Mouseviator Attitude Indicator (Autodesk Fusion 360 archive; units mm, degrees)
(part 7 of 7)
sketch "Wings!" plane through (0, 0, 0) normal (0, 1, 0) x axis (1, 0, 0)
  line L1 (520.32, -294.692) -> (520.32, -232.0032)
  line L2 (525.7316, -110.9551) -> (520.7141, -110.955)
  line L3 (520.7148, -79.9338) -> (500, -79.9338)
  line L4 (525.7287, -224.0816) -> (525.7316, -107.4016)
  line L5 (511.0057, -228.9584) -> (511.005, -224.0813)
  line L6 (511.005, -224.0813) -> (525.7287, -224.0816)
  line L7 (520.3202, -224.0815) -> (520.32, -232.0032)
  line L8 (520.7141, -110.955) -> (520.7148, -79.9338)
  line L9 (520.32, -228.9584) -> (511.0057, -228.9584)
  line L10 (500, -294.692) -> (500, -79.9338)
  line L11 (-520.32, -224.0816) -> (-520.32, -228.9584)
  line L12 (-526.6736, -224.1265) -> (-526.6736, -105.4918)
  line L13 (-513.7068, -224.0816) -> (-526.6736, -224.0816)
  line L14 (-522.3504, -105.4918) -> (-522.3504, -79.9338)
  line L15 (-526.6736, -105.4918) -> (-522.3504, -105.4918)
  line L16 (-522.3504, -79.9338) -> (-500, -79.9338)
  line L17 (-513.7068, -228.9584) -> (-513.7068, -224.0816)
  line L18 (-500, -294.692) -> (-500, -79.9338)
  line L19 (-520.32, -253.4337) -> (-520.32, -228.9584)
  line L20 (-520.32, -294.692) -> (-520.32, -253.4337)
  line L21 (-520.32, -228.9584) -> (-513.7068, -228.9584)
  curve K1 (172.9706, -420) -> (500, -294.703)
  line L22 (172.9706, -420) -> (0, -420)
  line L23 (-172.9706, -420) -> (0, -420)
  curve K2 (-172.9706, -420) -> (-500, -294.703)
  curve K3 (172.9706, -440.32) -> (520.32, -294.703)
  line L24 (172.9706, -440.32) -> (0, -440.32)
  line L25 (-172.9706, -440.32) -> (0, -440.32)
  curve K4 (-172.9706, -440.32) -> (-520.32, -294.703)
  line L26 (-499.9986, -293.6669) -> (-499.9986, -295.0337)
  line L27 (-520.3191, -293.2676) -> (-520.3191, -295.0337)
  line L28 (500, -294.692) -> (500, -294.703)
  line L29 (520.32, -294.692) -> (520.32, -294.703)
  line L30 (-500, -294.692) -> (-500, -294.703)
  line L31 (-520.32, -294.703) -> (-520.32, -294.692)
  circle C1 centre (511.1752, -213.2838) radius 3.81
  circle C2 centre (511.1752, -162.4838) radius 3.81
  circle C3 centre (511.1752, -105.3338) radius 3.81
  arc A1 centre (509.464, -135.4622) radius 12.7 clockwise from (500, -126.9933) to (500, -143.9311)
  circle C4 centre (-511.1752, -213.2838) radius 3.81
  circle C5 centre (-511.1752, -162.4838) radius 3.81
  circle C6 centre (-511.1752, -105.3338) radius 3.81
  arc A2 centre (-508.5619, -139.6363) radius 15.875 clockwise from (-500, -153.0045) to (-500, -126.268)
  circle C7 centre (-512.0079, -186.5029) radius 10.795
  point P23 (520.32, -228.9584)
  point P25 (520.3202, -224.0815)
  point P3 (511.005, -224.0813)
  point P4 (511.005, -224.0813)
  point P12 (525.7287, -224.0816)
  point P13 (525.7287, -224.0816)
  point P37 (-511.1752, -213.2838)
  point P38 (-511.1752, -105.3338)
  point P48 (-511.1752, -79.9338)
  point P41 (-511.1752, -162.4838)
  point P33 (-520.32, -224.0816)
  point P18 (520.32, -294.692)
  point P28 (500, -294.692)
  point P65 (-499.9986, -295.0337)
  point P67 (-520.3191, -295.0337)
  point P52 (500, -294.703)
  point P69 (500, -294.703)
  point P58 (-500, -294.703)
  point P70 (-500, -294.703)
  coincident P23 L1
  perpendicular L1 L9
  coincident P25 L6
  perpendicular L6 L7
  coincident P3 P4
  coincident P12 P13
  vertical L19
  horizontal L21
  vertical L17
  horizontal L13
  vertical P37 P38
  midpoint P48 L16
  vertical P38 P48
  vertical P37 P41
  coincident P33 L13
  perpendicular L11 L13
  equal C4 C5
  equal C5 C6
  perpendicular L3 L10
  horizontal P18 P28
  perpendicular L16 L18
  coincident K2 P65
  coincident K4 P67
  coincident P52 P69
  coincident P58 P70
  dimension "d889" diameter A1 = 25.4 (= "1")
  dimension "d890" distance P38 L16 = 25.4 (= "1")
  dimension "d891" distance P37 L16 = 133.35 (= "5.25")
  dimension "d892" distance P41 P48 = 82.55 (= "3.25")
  dimension "d893" diameter C7 = 21.59 (= "0.85")
  dimension "d894" diameter C4 = 7.62 (= "0.30")
  dimension "d895" = 20.32 (= "0.8")
sketch "Sketch8" plane through (0, 0, 0) normal (0, 1, 0) x axis (1, 0, 0)
sketch "Sketch7" plane through (0, 0, 0) normal (0, 1, 0) x axis (1, 0, 0)
canvas "Canvas8" sketch "Analog Master"
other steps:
create_component "CreateComponent1"
create_component "CreateComponent1"
remove_instance "RemoveInstance1"
create_component "CreateComponent2"

design "28BYJ-48"
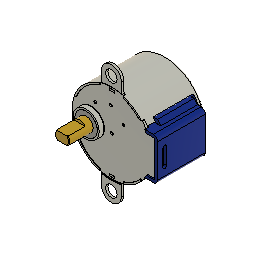
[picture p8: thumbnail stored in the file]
